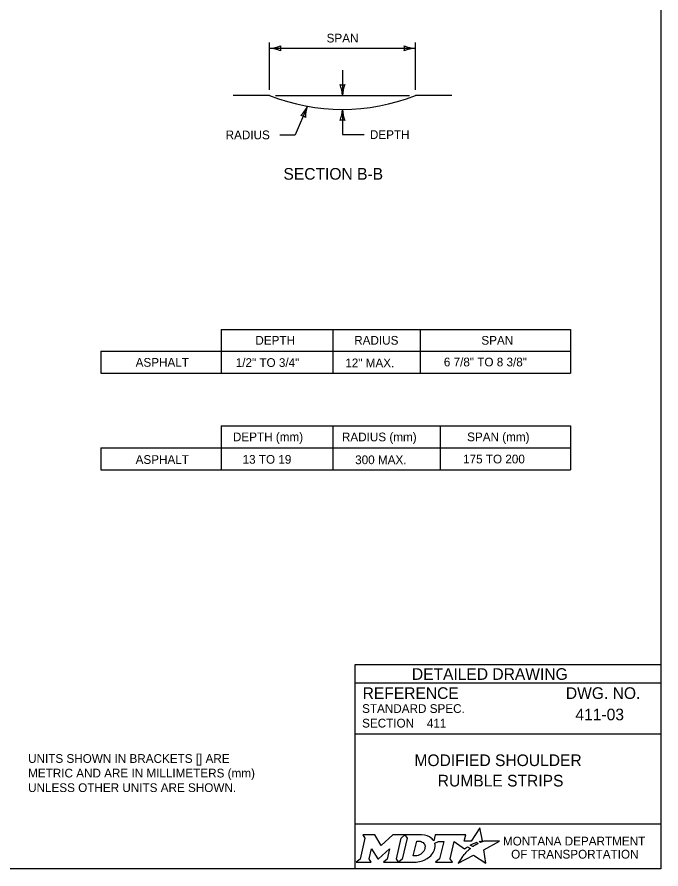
# Model space of a CAD drawing. Extents: x 49991.4 to 50021, y 49987.6 to 50011.4.
# Drawn here: x 50012.33 to 50016.75, y 49987.8 to 49993.64 of the extents above; entities that cross this region are included whole.
import ezdxf

# ---------------------------------------------------------------- set-up
doc = ezdxf.new("R2010")
doc.units = 0
for name, color, linetype in [('Default', 7, 'Continuous'), ('Level 1', 7, 'Continuous'), ('Level 2', 7, 'Continuous'), ('Level 3', 7, 'Continuous'), ('Level 5', 7, 'Continuous')]:
    doc.layers.add(name, color=color, linetype=linetype)

msp = doc.modelspace()

# ---------------------------------------------------------------- linework, layer by layer
at = {"layer": 'Default'}
for points in [[(50015.5126, 49987.9811), (50015.5023, 49987.9867), (50015.5139, 49987.9895), (50015.5255, 49987.9915), (50015.5081, 49988.0816), (50015.4486, 49987.9903), (50015.4013, 49987.9896), (50015.4116, 49988.0337), (50015.2024, 49988.0338), (50015.1923, 49987.9913), (50015.1865, 49987.9996)], [(50014.7056, 49988.0338), (50014.7197, 49988.0104), (50014.6862, 49987.8671), (50014.6605, 49987.8446), (50014.7621, 49987.8446), (50014.7486, 49987.8674), (50014.7648, 49987.9375), (50014.8085, 49987.8685), (50014.8138, 49987.8685), (50014.8889, 49987.938), (50014.8725, 49987.8669), (50014.8478, 49987.8449), (50014.9494, 49987.8449), (50014.9356, 49987.8682), (50014.9688, 49988.0106)], [(50014.9688, 49988.0106), (50014.9941, 49988.0338), (50014.9117, 49988.0338), (50014.8321, 49987.9608), (50014.7876, 49988.0335), (50014.7056, 49988.0338)], [(50015.1077, 49988.0338), (50014.9941, 49988.0338), (50015.0088, 49988.0109), (50014.9749, 49987.8671), (50014.9494, 49987.8449), (50015.06, 49987.8449)], [(50015.1317, 49987.9471), (50015.1305, 49987.939), (50015.1273, 49987.9297), (50015.1231, 49987.9215), (50015.1175, 49987.914), (50015.111, 49987.9071), (50015.1031, 49987.9008), (50015.0948, 49987.8961), (50015.0857, 49987.8922), (50015.0766, 49987.8899), (50015.0674, 49987.889), (50015.0515, 49987.889), (50015.0751, 49987.989), (50015.0911, 49987.989), (50015.0987, 49987.9884), (50015.1063, 49987.9865), (50015.1129, 49987.9835), (50015.119, 49987.9793), (50015.1238, 49987.9743), (50015.1275, 49987.9683), (50015.1302, 49987.9621), (50015.1318, 49987.9547), (50015.1318, 49987.9517), (50015.1317, 49987.9471)], [(50015.1991, 49987.9747), (50015.2237, 49987.9878), (50015.2606, 49987.9878), (50015.232, 49987.8673), (50015.2045, 49987.8446), (50015.3207, 49987.8446), (50015.3037, 49987.8675), (50015.3319, 49987.9877), (50015.4032, 49987.936), (50015.4243, 49987.9511), (50015.444, 49987.9402)], [(50015.3882, 49987.8843), (50015.3729, 49987.8599), (50015.3682, 49987.8524), (50015.3624, 49987.8438), (50015.3601, 49987.8395), (50015.4654, 49987.8926), (50015.5493, 49987.8375), (50015.5362, 49987.9302), (50015.6431, 49987.9886), (50015.5938, 49987.9894), (50015.5637, 49987.9898), (50015.5429, 49987.9901), (50015.5361, 49987.9886), (50015.5312, 49987.9874), (50015.5228, 49987.9851), (50015.5126, 49987.9811)], [(50015.4622, 49987.9535), (50015.4598, 49987.9518), (50015.4415, 49987.9614), (50015.4518, 49987.9671), (50015.4559, 49987.9693), (50015.4645, 49987.9733), (50015.4702, 49987.9759), (50015.4781, 49987.9789), (50015.4854, 49987.9816), (50015.4972, 49987.9742), (50015.4932, 49987.9721), (50015.4886, 49987.9696), (50015.4844, 49987.9674), (50015.4794, 49987.9645), (50015.4775, 49987.9634), (50015.4748, 49987.9618), (50015.4723, 49987.9604), (50015.47, 49987.9588), (50015.4674, 49987.957), (50015.4647, 49987.9552), (50015.4622, 49987.9535)], [(50015.4021, 49987.9004), (50015.4021, 49987.9004)], [(50015.1057, 49987.8522), (50015.1141, 49987.8548), (50015.1271, 49987.8602), (50015.1475, 49987.8712)]]:
    msp.add_lwpolyline(points, dxfattribs=at)
for centre, radius, start, end in [((50015.1308, 49987.9554), 0.0709, 339.53292, 15.85821), ((50015.0868, 49987.9727), 0.1183, 300.91025, 339.13831)]:
    msp.add_arc(centre, radius, start, end, dxfattribs=at)
for centre, major_axis, ratio, start_param, end_param in [((50015.1056, 49987.9864), (0.0834, -0.0037), 0.568097, 0.61298, 1.570796), ((50015.1612, 49987.9937), (0.0361, -0.0295), 0.469099, 1.225588, 1.570796), ((50015.4329, 49987.9305), (-0.0112, -0.0097), 0.021651, 3.157348, 6.283185), ((50015.3952, 49987.8923), (-0.00694, -0.00806), 0.008222, 0, 3.137361), ((50015.4119, 49987.9106), (-0.0098, -0.0102), 0.016458, 3.141593, 6.279097), ((50015.0603, 49987.9932), (0, 0.1484), 0.987302, 3.139398, 3.456847)]:
    msp.add_ellipse(centre, major_axis=major_axis, ratio=ratio, start_param=start_param, end_param=end_param, dxfattribs=at)
at = {"layer": 'Level 1'}
for p, q in [((50014.0656, 49993.106), (50013.8156, 49993.106)), ((50015.3156, 49993.106), (50015.0656, 49993.106))]:
    msp.add_line(p, q, dxfattribs=at)
msp.add_lwpolyline([(49999.3835, 49998.9992), (50016.7501, 49998.9992), (50016.7501, 49987.7988), (49999.3835, 49987.7988)], close=True, dxfattribs=at)
msp.add_arc((50014.5656, 49994.3742), 1.3633, 248.48407, 291.51593, dxfattribs=at)
at = {"layer": 'Level 2'}
for p, q in [((50013.7327, 49991.501), (50016.1292, 49991.501)), ((50013.7327, 49991.501), (50013.7327, 49991.201)), ((50014.4996, 49991.501), (50014.4996, 49991.201)), ((50015.0996, 49991.501), (50015.0996, 49991.201)), ((50016.1292, 49991.501), (50016.1292, 49991.201)), ((50012.9077, 49991.351), (50012.9077, 49991.201)), ((50012.9077, 49991.351), (50013.7327, 49991.351)), ((50013.7327, 49991.351), (50016.1292, 49991.351)), ((50013.7327, 49991.351), (50015.6327, 49991.351)), ((50013.7327, 49991.351), (50015.6327, 49991.351)), ((50012.9077, 49991.201), (50016.1292, 49991.201)), ((50013.7327, 49991.201), (50015.6327, 49991.201)), ((50013.7327, 49990.8384), (50016.1292, 49990.8384)), ((50013.7327, 49990.8384), (50013.7327, 49990.5384)), ((50014.4996, 49990.8384), (50014.4996, 49990.5384)), ((50015.2366, 49990.8384), (50015.2366, 49990.5384)), ((50016.1292, 49990.8384), (50016.1292, 49990.5384)), ((50012.9077, 49990.6884), (50012.9077, 49990.5384)), ((50012.9077, 49990.6884), (50016.1292, 49990.6884)), ((50012.9077, 49990.5384), (50016.1292, 49990.5384))]:
    msp.add_line(p, q, dxfattribs=at)
at = {"layer": 'Level 3'}
for p, q in [((50014.0656, 49993.146), (50014.0656, 49993.4698)), ((50014.0656, 49993.4298), (50015.0656, 49993.4298)), ((50015.0656, 49993.146), (50015.0656, 49993.4698)), ((50014.5656, 49993.2794), (50014.5656, 49993.106)), ((50014.1056, 49993.106), (50015.0256, 49993.106)), ((50014.326, 49993.0322), (50014.2415, 49992.8357)), ((50014.5656, 49993.011), (50014.5656, 49992.8376)), ((50014.136, 49992.8357), (50014.2415, 49992.8357)), ((50014.5656, 49992.8376), (50014.7138, 49992.8376))]:
    msp.add_line(p, q, dxfattribs=at)
for centre, radius, start, end in [((50014.0542, 49993.6625), 0.233, 272.82731, 292.07716), ((50014.0565, 49993.2076), 0.2223, 67.45601, 87.63952), ((50014.1939, 49993.4298), 0.0548, 162.13882, 197.86118), ((50015.0748, 49993.6519), 0.2223, 247.45601, 267.63952), ((50014.9374, 49993.4298), 0.0548, 342.13882, 17.86118), ((50015.0771, 49993.197), 0.233, 92.82731, 112.07716), ((50014.5656, 49993.2342), 0.0548, 252.13882, 287.86118), ((50014.3329, 49993.0945), 0.233, 2.82731, 22.07716), ((50014.7878, 49993.0968), 0.2223, 157.45601, 177.63952), ((50014.1256, 49993.1283), 0.2223, 314.19076, 334.37427), ((50014.5444, 49992.9508), 0.233, 159.56206, 178.81191), ((50014.2754, 49992.9144), 0.0548, 48.87357, 84.59593), ((50014.3435, 49993.0201), 0.2223, 337.45601, 357.63952), ((50014.7984, 49993.0224), 0.233, 182.82731, 202.07716), ((50014.5656, 49992.8827), 0.0548, 72.13882, 107.86118)]:
    msp.add_arc(centre, radius, start, end, dxfattribs=at)
at = {"layer": 'Level 5'}
for p, q in [((50016.7501, 49989.1988), (50014.6501, 49989.1988)), ((50014.6501, 49989.1988), (50014.6501, 49987.7988)), ((50016.7501, 49989.0738), (50014.6501, 49989.0738)), ((50016.3862, 49988.8587), (50016.3862, 49988.8587)), ((50015.1444, 49988.7993), (50015.1444, 49988.7993)), ((50016.7501, 49988.7238), (50014.6501, 49988.7238)), ((50015.7001, 49988.4747), (50015.7001, 49988.4747)), ((50016.7501, 49988.1057), (50014.6501, 49988.1057))]:
    msp.add_line(p, q, dxfattribs=at)

# ---------------------------------------------------------------- texts
at = {"layer": 'Default'}
for s, p in [('MONTANA DEPARTMENT', (50015.6663, 49987.96)), ('OF TRANSPORTATION', (50015.7225, 49987.87))]:
    msp.add_text(s, height=0.06, dxfattribs=at).set_placement(p)
at = {"layer": 'Level 2'}
for s, height, p in [('SPAN', 0.06, (50014.457, 49993.4698)), ('RADIUS', 0.06, (50013.7644, 49992.8057)), ('DEPTH', 0.06, (50014.7538, 49992.8076)), ('SECTION B-B', 0.08, (50014.1608, 49992.5284)), ('DEPTH', 0.06, (50013.9682, 49991.3962)), ('RADIUS', 0.06, (50014.6463, 49991.3962)), ('SPAN', 0.06, (50015.5183, 49991.396)), ('ASPHALT', 0.06, (50013.1471, 49991.2448)), ('1/2" TO 3/4"', 0.06, (50013.8336, 49991.2434)), ('12" MAX.', 0.06, (50014.585, 49991.2411)), ('6 7/8" TO 8 3/8"', 0.06, (50015.261, 49991.2473)), ('DEPTH (mm)', 0.06, (50013.8144, 49990.7336)), ('RADIUS (mm)', 0.06, (50014.562, 49990.733)), ('SPAN (mm)', 0.06, (50015.4208, 49990.7336)), ('ASPHALT', 0.06, (50013.1471, 49990.578)), ('13 TO 19', 0.06, (50013.8807, 49990.5794)), ('300 MAX.', 0.06, (50014.6528, 49990.5763)), ('175 TO 200', 0.06, (50015.3929, 49990.5816)), ('411-03', 0.08, (50016.1635, 49988.8187)), ('411', 0.06, (50015.1444, 49988.7693)), ('UNITS SHOWN IN BRACKETS [] ARE ', 0.06, (50012.4097, 49988.5266)), ('MODIFIED SHOULDER', 0.08, (50015.0594, 49988.5047)), ('METRIC AND ARE IN MILLIMETERS (mm) ', 0.06, (50012.4097, 49988.4266)), ('RUMBLE STRIPS', 0.08, (50015.2193, 49988.3647)), ('UNLESS OTHER UNITS ARE SHOWN.', 0.06, (50012.4097, 49988.3266))]:
    msp.add_text(s, height=height, dxfattribs=at).set_placement(p)
at = {"layer": 'Level 5'}
for s, height, p in [('DETAILED DRAWING', 0.0799, (50015.0418, 49989.0963)), ('REFERENCE', 0.08, (50014.7037, 49988.9654)), ('DWG. NO.', 0.08, (50016.0979, 49988.9654)), ('STANDARD SPEC.', 0.06, (50014.7004, 49988.8694)), ('SECTION', 0.06, (50014.7004, 49988.7694))]:
    msp.add_text(s, height=height, dxfattribs=at).set_placement(p)

doc.saveas('drawing.dxf')
